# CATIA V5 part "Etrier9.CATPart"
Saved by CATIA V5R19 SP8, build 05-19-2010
Part number: Etrier9
Bounding box of the stored display mesh (mm): x -124 to -116, y 57.868 to 96.964, z -27.66 to 6.428
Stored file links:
  G:\EU_thinkMotion\CFAO_2010\MMS_groupe2\MMS_groupe2\A reprendre\jcauchy\Etrier9.CATPart
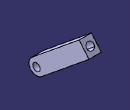
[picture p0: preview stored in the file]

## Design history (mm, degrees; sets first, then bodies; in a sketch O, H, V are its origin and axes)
Parameters
  Rayonfixation_etrier9 = 2.5 mm
  Hauteuretrier_etrier9 = 8 mm
  Longueuretrier_etrier9 = 40 mm
  Largeuretrier_etrier9 = 10 mm
  Rayontige_etrier9 = 5 mm
  Profondeurtige_etrier9 = 20 mm
Set1
  Plane1: stored without definition
  Sketch1 on Plane1, origin (-120, 0, 0), H (0, 1, 0), V (0, 0, 1)
    point P1 (113.273, -15.0005)
    reference projected point E1 (113.273, -15.0005) from Point1
    arc A1 centre (62.8038, -22.7243) radius 5 from (59.6441, -18.8492) to (65.9634, -26.5995) ccw
    line L1 (59.6441, -18.8492) -> (90.6451, 6.428)
    line L2 (65.9634, -26.5995) -> (96.9644, -1.3223)
    line L3 (90.6451, 6.428) -> (96.9644, -1.3223)
    distance P1 E1 = 0
    length L3 = 10 {= Largeuretrier_etrier9}
    length L2 = 40 {= Longueuretrier_etrier9}
    tangency: L1 A1, L2 A1
    perpendicularity: L3 L2, L1 L3
  Point1: stored without definition
  Plane2: stored without definition
  Plane3: stored without definition
  Point2: stored without definition
  Plane4: stored without definition
  Point3 to Point5: stored without definition
Body1 (main body)
  Pad1: profile Sketch1, direction (1, 0, 0), length 4, mirrored extent
  Sketch2 on end face of Pad1, origin (-116, 69.6573, -18.7387), H (0, 1, 0), V (0, 0, 1)
    point P1 (-6.8536, -3.9856)
    reference projected arc E1 centre (-6.8536, -3.9856) radius 5 from (-10.0132, -0.1105) to (-3.6939, -7.8607) ccw from edge [face of Pad1 from Sketch1.A1 | end face of Pad1]
    distance P1 E1 = 5 {= Largeuretrier_etrier9 /2}
  Hole1: placed by Sketch2, at (-116, 62.8038, -22.7243) direction (-1, 0, 0), diameter 5 {= Rayonfixation_etrier9 *2}, depth 10
  Sketch3 on face of Pad1 from Sketch1.L3, origin (-120.2672, 94.9193, 1.1859), H (1, 0, 0), V (0, 0.6319, -0.775)
    point P1 (0.2672, -1.7637)
    reference projected line E1 (4.2672, 3.2363) -> (4.2672, -6.7637) from edge [face of Pad1 from Sketch1.L3 | end face of Pad1]
    reference projected line E2 (-3.7328, -6.7637) -> (4.2672, -6.7637) from edge [face of Pad1 from Sketch1.L1 | face of Pad1 from Sketch1.L3]
    distance P1 E1 = 4 {= Hauteuretrier_etrier9 /2}
    distance P1 E2 = 5 {= Largeuretrier_etrier9 /2}
  Hole2: placed by Sketch3, at (-120, 93.8048, 2.5529) direction (0, -0.775, -0.6319), diameter 5 {= Rayontige_etrier9}, depth 20 {= Profondeurtige_etrier9}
